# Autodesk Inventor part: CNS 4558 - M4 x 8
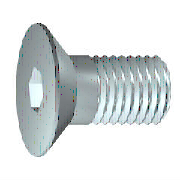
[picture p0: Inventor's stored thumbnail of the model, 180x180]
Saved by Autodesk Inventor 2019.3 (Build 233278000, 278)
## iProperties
Created: 2018-01
Part Number: CNS 4558 - M4 x 8
Material: Ocel, měkká
Description: Šroub se zápustnou hlavou
Document SubType Name: Modeling
Standard: CNS 4558
Designer: B-hon
Standards Organization: CNS
Language: cs-CZ
Size Designation: M4 x 8
Categories: <MemberInstance><Categories><Category DisplayName="Spojovací materiál" InternalName="e4da775c-781d-43d5-af7c-5136215cf5a6" Mnemonic="FSTN"><Category DisplayName
Density: 7.85 g/cm^3
Appearance: Pololeštěná
IsCustomPart: 0
Author: B-hon
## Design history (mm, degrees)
body "Solid1"
revolve "Těleso" stored, may be unused: angle "d13" = 90 deg
sketch "Náčrt2"
  geometry: L1 (0, -5.6)-(0, 5.6) reference; L2 (-5.6, 0)-(5.6, 0) reference; L3 (1.443, 0)-(0.722, -1.25); L4 (0.722, -1.25)-(-0.722, -1.25); L5 (-0.722, -1.25)-(-1.443, 0); L6 (-1.443, 0)-(-0.722, 1.25); L7 (-0.722, 1.25)-(0.722, 1.25); L8 (0.722, 1.25)-(1.443, 0); A1 r 1.443 centre (0, 0) between (0, 1.443) and (1.443, 0) reference; 2 further points
  constraints: 12 end point, 2 coincident, 2 point on circle, 2 point on line, 12 other
extrude "Drážka" join sketch "Náčrt2" taper "d14" = 0 deg; stored distance "d30" = 10
feature "Závit" dims "d15" = 3.6 (= GEL), "d16" = 0
chamfer "Zkosení1" distance "d17" = 0.42941 (= -0.5 x SPD + 0.5 x GD); stored, may be unused: second distance "d18" = 0.42941 (= GUL), angle "d39" = 45 deg
workplane "Work Plane1"
sketch "Náčrt1"
  geometry: L1 (8, 0)-(8, 2); L2 (8, 2)-(4.4, 2); L3 (4.4, 2)-(3.971, 2); L4 (0, 4)-(0, 1.443); L5 (0, 1.443)-(1.8, 1.443); L6 (1.8, 1.443)-(2.633, 0); L7 (2.633, 0)-(8, 0); L8 (0, 4)-(0.3, 4); L9 (0.3, 4)-(2.3, 2); L10 (3.971, 2)-(2.3, 2); L11 (4.4, 2)-(2.3, 2); L12 (2.3, 2)-(2.3, 2); L13 (-1.6, 0)-(9.6, 0) reference; L14 (0, -0.8)-(0, 4.8) reference
  constraints: 24 end point, 4 collinear, 3 parallel
  dimensions: "d0" = 8 distance between parallel lines of L4 L1 (= NLG); "d1" = 3.6 distance from line of L2.end L1 (= GEL); "d2" = 1.8 distance from line of L5.end L4 (= INTI); "d3" = 4 diameter of L2 L7 (= GD); "d6" = 2.3 distance from line of L9.end L4 (= KOH); "d7" = 45 deg angle of L9 L7 (= 0.5 x SEWI); "d8" = 2.88675 diameter of L5 L7 (= 1.1547 x SW); "d9" = 60 deg angle of L6 L7; "d10" = 8 diameter of L8 L7 (= KOD); "d11" = 4 diameter of L10 L7 (= BDM); "d12" = 0.42941 distance of L3.end L2.end (= GAL)
other parameters: "NLG" = 8 [user parameter; used in 1 equation term], "INTI" = 1.8 [user parameter; used in 1 equation term], "GEL" = 3.6 [user parameter; used in 2 equation terms], "GAL" = 0.42941 (= 0.61345 x PTC) [user parameter; used in 1 equation term], "KOH" = 2.3 [user parameter; used in 1 equation term], "KOD" = 8 [user parameter; used in 1 equation term], "GUL" = 0.42941 (= 0.61345 x PTC) [user parameter; used in 1 equation term], "SPD" = 3.14117 (= NND - 1.2269 x PTC) [user parameter; used in 1 equation term], "BDM" = 4 (= NND) [user parameter; used in 1 equation term], "GD" = 4 (= NND) [user parameter; used in 2 equation terms], "SEWI" = 90 deg [user parameter; used in 1 equation term], "d20" = 0, "SW" = 2.5 [user parameter; used in 2 equation terms], "d43" = 0, "d44" = 0, "TOA" = 30 deg [user parameter], "GD1" = 3.14117 (= THREADDIA - 1.2269 x PTC) [user parameter], "EPV" = 4.3 [user parameter], "THREADDIA" = 4 [user parameter; used in 1 equation term], "TPU" = 14.28571 (computed from PTC) [user parameter], "PTC" = 0.7 [user parameter; used in 5 equation terms], "NND" = 4 [user parameter; used in 3 equation terms], "E0" = 2.8875 (= 1.155 x SW) [user parameter]
